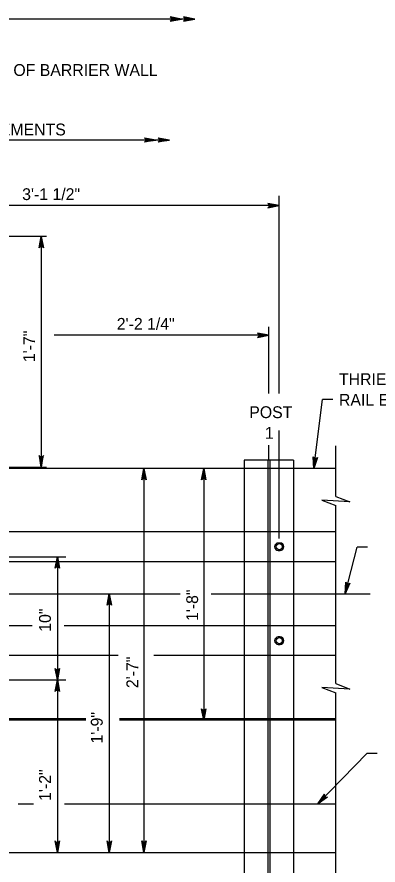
# Model space of a CAD drawing. Extents: x 632007860 to 635435983, y 295418622 to 297794622.
# Drawn here: x 634021018 to 634113990, y 295535766 to 295754298 of the extents above; entities that cross this region are included whole.
import ezdxf

# ---------------------------------------------------------------- set-up
doc = ezdxf.new("R2010")
doc.units = 0
for name, color, linetype in [('8', 7, 'Continuous'), ('S-ABUT', 7, 'Continuous'), ('S-DETL-DIMS', 7, 'Continuous'), ('S-DETL-T120', 7, 'Continuous'), ('S-STEL', 7, 'Continuous')]:
    doc.layers.add(name, color=color, linetype=linetype)

msp = doc.modelspace()

# ---------------------------------------------------------------- linework, layer by layer
at = {"layer": '8'}
for p, q in [((634085888, 295640078), (634085888, 295643944)), ((633884925, 295605683), (634063043, 295605683)), ((634070984, 295605683), (634111925, 295605683))]:
    msp.add_line(p, q, dxfattribs=at)
at = {"layer": 'S-ABUT'}
for p, q in [((634021348, 295551503), (634025281, 295551503)), ((634033228, 295551503), (634103091, 295551503)), ((634001942, 295539008), (634103091, 295539008))]:
    msp.add_line(p, q, dxfattribs=at)
at = {"layer": 'S-DETL-DIMS'}
for p, q in [((634066858, 295753743), (633896300, 295753743)), ((634060314, 295722580), (633946329, 295722580)), ((634088543, 295657244), (634088543, 295708236)), ((634088543, 295705697), (633969689, 295705697)), ((634028634, 295697741), (633925374, 295697741)), ((634027266, 295697741), (634027266, 295638295)), ((634085888, 295657266), (634085888, 295674446)), ((634085888, 295672286), (634030560, 295672286)), ((634097449, 295637961), (634099673, 295655702)), ((634102319, 295655702), (634099673, 295655702)), ((634088543, 295619944), (634088543, 295647710)), ((634103129, 295630769), (634103129, 295643821)), ((634053703, 295637960), (634053703, 295622872)), ((634069125, 295637960), (634069125, 295622872)), ((634103129, 295588901), (634103129, 295628388)), ((634053703, 295622872), (634053703, 295539008)), ((634069125, 295622872), (634069125, 295573092)), ((634105488, 295605683), (634108626, 295617710)), ((634111273, 295617710), (634108626, 295617710)), ((634002178, 295615208), (634033589, 295615208)), ((634031448, 295615208), (634031448, 295539008)), ((634040738, 295605683), (634046878, 295605683)), ((634044792, 295605683), (634044792, 295539008)), ((634103129, 295582550), (634103129, 295588901)), ((634002606, 295583470), (634033589, 295583470)), ((634103091, 295488138), (634103091, 295580169)), ((634098506, 295551530), (634111093, 295564494)), ((634113740, 295564494), (634111093, 295564494)), ((634003476, 295539008), (634043513, 295539008))]:
    msp.add_line(p, q, dxfattribs=at)
for points in [[(634063389, 295753743), (634060430, 295754298), (634060544, 295754219), (634060658, 295754140), (634060716, 295754041), (634060775, 295753942), (634060792, 295753843), (634060809, 295753743), (634060792, 295753644), (634060775, 295753545), (634060716, 295753446), (634060658, 295753346), (634060544, 295753267), (634060430, 295753188), (634063389, 295753743), (634060544, 295753267), (634060658, 295753346), (634063389, 295753743), (634060716, 295753446), (634060775, 295753545), (634063389, 295753743), (634060792, 295753644), (634060809, 295753743), (634063389, 295753743), (634060792, 295753843), (634060775, 295753942), (634063389, 295753743), (634060716, 295754041), (634060658, 295754140), (634063389, 295753743), (634060544, 295754219)], [(634066858, 295753743), (634063898, 295754298), (634064012, 295754219), (634064126, 295754140), (634064185, 295754041), (634064244, 295753942), (634064261, 295753843), (634064278, 295753743), (634064261, 295753644), (634064244, 295753545), (634064185, 295753446), (634064126, 295753346), (634064012, 295753267), (634063898, 295753188), (634066858, 295753743), (634064012, 295753267), (634064126, 295753346), (634066858, 295753743), (634064185, 295753446), (634064244, 295753545), (634066858, 295753743), (634064261, 295753644), (634064278, 295753743), (634066858, 295753743), (634064261, 295753843), (634064244, 295753942), (634066858, 295753743), (634064185, 295754041), (634064126, 295754140), (634066858, 295753743), (634064012, 295754219)], [(634056783, 295722580), (634053823, 295722025), (634053937, 295722104), (634054051, 295722183), (634054110, 295722282), (634054169, 295722382), (634054186, 295722481), (634054203, 295722580), (634054186, 295722679), (634054169, 295722779), (634054110, 295722878), (634054051, 295722977), (634053937, 295723056), (634053823, 295723135), (634056783, 295722580), (634053937, 295723056), (634054051, 295722977), (634056783, 295722580), (634054110, 295722878), (634054169, 295722779), (634056783, 295722580), (634054186, 295722679), (634054203, 295722580), (634056783, 295722580), (634054186, 295722481), (634054169, 295722382), (634056783, 295722580), (634054110, 295722282), (634054051, 295722183), (634056783, 295722580), (634053937, 295722104)], [(634060314, 295722580), (634057355, 295722025), (634057469, 295722104), (634057583, 295722183), (634057641, 295722282), (634057700, 295722382), (634057717, 295722481), (634057734, 295722580), (634057717, 295722679), (634057700, 295722779), (634057641, 295722878), (634057583, 295722977), (634057469, 295723056), (634057355, 295723135), (634060314, 295722580), (634057469, 295723056), (634057583, 295722977), (634060314, 295722580), (634057641, 295722878), (634057700, 295722779), (634060314, 295722580), (634057717, 295722679), (634057734, 295722580), (634060314, 295722580), (634057717, 295722481), (634057700, 295722382), (634060314, 295722580), (634057641, 295722282), (634057583, 295722183), (634060314, 295722580), (634057469, 295722104)], [(634088543, 295705697), (634085584, 295706252), (634085698, 295706173), (634085812, 295706094), (634085870, 295705995), (634085929, 295705896), (634085946, 295705796), (634085963, 295705697), (634085946, 295705598), (634085929, 295705499), (634085870, 295705400), (634085812, 295705300), (634085698, 295705221), (634085584, 295705142), (634088543, 295705697), (634085698, 295705221), (634085812, 295705300), (634088543, 295705697), (634085870, 295705400), (634085929, 295705499), (634088543, 295705697), (634085946, 295705598), (634085963, 295705697), (634088543, 295705697), (634085946, 295705796), (634085929, 295705896), (634088543, 295705697), (634085870, 295705995), (634085812, 295706094), (634088543, 295705697), (634085698, 295706173)], [(634027266, 295697741), (634027821, 295694781), (634027663, 295695009), (634027464, 295695127), (634027266, 295695161), (634027068, 295695127), (634026869, 295695009), (634026711, 295694781), (634027266, 295697741), (634026869, 295695009), (634027068, 295695127), (634027266, 295697741), (634027266, 295695161), (634027464, 295695127), (634027266, 295697741), (634027663, 295695009)], [(634085888, 295672286), (634082928, 295672841), (634083042, 295672762), (634083156, 295672683), (634083215, 295672584), (634083274, 295672485), (634083291, 295672386), (634083308, 295672286), (634083291, 295672187), (634083274, 295672088), (634083215, 295671989), (634083156, 295671890), (634083042, 295671811), (634082928, 295671732), (634085888, 295672286), (634083042, 295671811), (634083156, 295671890), (634085888, 295672286), (634083215, 295671989), (634083274, 295672088), (634085888, 295672286), (634083291, 295672187), (634083308, 295672286), (634085888, 295672286), (634083291, 295672386), (634083274, 295672485), (634085888, 295672286), (634083215, 295672584), (634083156, 295672683), (634085888, 295672286), (634083042, 295672762)], [(634027266, 295638295), (634027821, 295641255), (634027742, 295641141), (634027663, 295641027), (634027564, 295640968), (634027464, 295640909), (634027365, 295640892), (634027266, 295640875), (634027167, 295640892), (634027068, 295640909), (634026968, 295640968), (634026869, 295641027), (634026790, 295641141), (634026711, 295641255), (634027266, 295638295), (634026790, 295641141), (634026869, 295641027), (634027266, 295638295), (634026968, 295640968), (634027068, 295640909), (634027266, 295638295), (634027167, 295640892), (634027266, 295640875), (634027266, 295638295), (634027365, 295640892), (634027464, 295640909), (634027266, 295638295), (634027564, 295640968), (634027663, 295641027), (634027266, 295638295), (634027742, 295641141)], [(634097449, 295637961), (634097304, 295640968), (634097366, 295640845), (634097429, 295640721), (634097519, 295640649), (634097610, 295640577), (634097706, 295640547), (634097801, 295640516), (634097902, 295640520), (634098003, 295640523), (634098109, 295640568), (634098215, 295640612), (634098309, 295640715), (634098403, 295640817), (634097449, 295637961), (634098309, 295640715), (634098215, 295640612), (634097449, 295637961), (634098109, 295640568), (634098003, 295640523), (634097449, 295637961), (634097902, 295640520), (634097801, 295640516), (634097449, 295637961), (634097706, 295640547), (634097610, 295640577), (634097449, 295637961), (634097519, 295640649), (634097429, 295640721), (634097449, 295637961), (634097366, 295640845)], [(634053703, 295637960), (634054258, 295635001), (634054100, 295635229), (634053902, 295635346), (634053703, 295635380), (634053505, 295635346), (634053307, 295635229), (634053149, 295635001), (634053703, 295637960), (634053307, 295635229), (634053505, 295635346), (634053703, 295637960), (634053703, 295635380), (634053902, 295635346), (634053703, 295637960), (634054100, 295635229)], [(634069125, 295637960), (634069680, 295635001), (634069522, 295635229), (634069324, 295635346), (634069125, 295635380), (634068927, 295635346), (634068729, 295635229), (634068571, 295635001), (634069125, 295637960), (634068729, 295635229), (634068927, 295635346), (634069125, 295637960), (634069125, 295635380), (634069324, 295635346), (634069125, 295637960), (634069522, 295635229)], [(634103129, 295630769), (634106700, 295629319), (634099557, 295629751), (634103129, 295628388)], [(634031448, 295615208), (634032002, 295612248), (634031923, 295612362), (634031844, 295612476), (634031745, 295612535), (634031646, 295612594), (634031547, 295612611), (634031448, 295612628), (634031348, 295612611), (634031249, 295612594), (634031150, 295612535), (634031051, 295612476), (634030972, 295612362), (634030893, 295612248), (634031448, 295615208), (634030972, 295612362), (634031051, 295612476), (634031448, 295615208), (634031150, 295612535), (634031249, 295612594), (634031448, 295615208), (634031348, 295612611), (634031448, 295612628), (634031448, 295615208), (634031547, 295612611), (634031646, 295612594), (634031448, 295615208), (634031745, 295612535), (634031844, 295612476), (634031448, 295615208), (634031923, 295612362)], [(634105488, 295605683), (634105698, 295608686), (634105746, 295608556), (634105794, 295608426), (634105875, 295608344), (634105956, 295608262), (634106048, 295608220), (634106139, 295608179), (634106240, 295608170), (634106340, 295608162), (634106451, 295608193), (634106562, 295608225), (634106667, 295608316), (634106772, 295608406), (634105488, 295605683), (634106667, 295608316), (634106562, 295608225), (634105488, 295605683), (634106451, 295608193), (634106340, 295608162), (634105488, 295605683), (634106240, 295608170), (634106139, 295608179), (634105488, 295605683), (634106048, 295608220), (634105956, 295608262), (634105488, 295605683), (634105875, 295608344), (634105794, 295608426), (634105488, 295605683), (634105746, 295608556)], [(634044792, 295605683), (634045347, 295602723), (634045268, 295602837), (634045189, 295602951), (634045090, 295603010), (634044990, 295603069), (634044891, 295603086), (634044792, 295603103), (634044693, 295603086), (634044593, 295603069), (634044494, 295603010), (634044395, 295602951), (634044316, 295602837), (634044237, 295602723), (634044792, 295605683), (634044316, 295602837), (634044395, 295602951), (634044792, 295605683), (634044494, 295603010), (634044593, 295603069), (634044792, 295605683), (634044693, 295603086), (634044792, 295603103), (634044792, 295605683), (634044891, 295603086), (634044990, 295603069), (634044792, 295605683), (634045090, 295603010), (634045189, 295602951), (634044792, 295605683), (634045268, 295602837)], [(634031448, 295583470), (634030893, 295586430), (634030972, 295586316), (634031051, 295586202), (634031150, 295586143), (634031249, 295586084), (634031348, 295586067), (634031448, 295586050), (634031547, 295586067), (634031646, 295586084), (634031745, 295586143), (634031844, 295586202), (634031923, 295586316), (634032002, 295586430), (634031448, 295583470), (634031923, 295586316), (634031844, 295586202), (634031448, 295583470), (634031745, 295586143), (634031646, 295586084), (634031448, 295583470), (634031547, 295586067), (634031448, 295586050), (634031448, 295583470), (634031348, 295586067), (634031249, 295586084), (634031448, 295583470), (634031150, 295586143), (634031051, 295586202), (634031448, 295583470), (634030972, 295586316)], [(634031448, 295583470), (634032002, 295580511), (634031923, 295580625), (634031844, 295580739), (634031745, 295580798), (634031646, 295580857), (634031547, 295580874), (634031448, 295580891), (634031348, 295580874), (634031249, 295580857), (634031150, 295580798), (634031051, 295580739), (634030972, 295580625), (634030893, 295580511), (634031448, 295583470), (634030972, 295580625), (634031051, 295580739), (634031448, 295583470), (634031150, 295580798), (634031249, 295580857), (634031448, 295583470), (634031348, 295580874), (634031448, 295580891), (634031448, 295583470), (634031547, 295580874), (634031646, 295580857), (634031448, 295583470), (634031745, 295580798), (634031844, 295580739), (634031448, 295583470), (634031923, 295580625)], [(634103129, 295582550), (634106700, 295581100), (634099557, 295581532), (634103129, 295580169)], [(634069125, 295573092), (634068571, 295576051), (634068729, 295575823), (634068927, 295575706), (634069125, 295575672), (634069324, 295575706), (634069522, 295575823), (634069680, 295576051), (634069125, 295573092), (634069522, 295575823), (634069324, 295575706), (634069125, 295573092), (634069125, 295575672), (634068927, 295575706), (634069125, 295573092), (634068729, 295575823)], [(634098506, 295551530), (634100179, 295554034), (634100155, 295553897), (634100132, 295553760), (634100162, 295553649), (634100192, 295553538), (634100251, 295553456), (634100310, 295553374), (634100393, 295553317), (634100476, 295553260), (634100588, 295553233), (634100700, 295553205), (634100836, 295553232), (634100972, 295553258), (634098506, 295551530), (634100836, 295553232), (634100700, 295553205), (634098506, 295551530), (634100588, 295553233), (634100476, 295553260), (634098506, 295551530), (634100393, 295553317), (634100310, 295553374), (634098506, 295551530), (634100251, 295553456), (634100192, 295553538), (634098506, 295551530), (634100162, 295553649), (634100132, 295553760), (634098506, 295551530), (634100155, 295553897)], [(634031448, 295539008), (634030893, 295541967), (634030972, 295541853), (634031051, 295541739), (634031150, 295541680), (634031249, 295541621), (634031348, 295541604), (634031448, 295541587), (634031547, 295541604), (634031646, 295541621), (634031745, 295541680), (634031844, 295541739), (634031923, 295541853), (634032002, 295541967), (634031448, 295539008), (634031923, 295541853), (634031844, 295541739), (634031448, 295539008), (634031745, 295541680), (634031646, 295541621), (634031448, 295539008), (634031547, 295541604), (634031448, 295541587), (634031448, 295539008), (634031348, 295541604), (634031249, 295541621), (634031448, 295539008), (634031150, 295541680), (634031051, 295541739), (634031448, 295539008), (634030972, 295541853)], [(634031448, 295539008), (634030893, 295541967), (634030972, 295541853), (634031051, 295541739), (634031150, 295541680), (634031249, 295541621), (634031348, 295541604), (634031448, 295541587), (634031547, 295541604), (634031646, 295541621), (634031745, 295541680), (634031844, 295541739), (634031923, 295541853), (634032002, 295541967), (634031448, 295539008), (634031923, 295541853), (634031844, 295541739), (634031448, 295539008), (634031745, 295541680), (634031646, 295541621), (634031448, 295539008), (634031547, 295541604), (634031448, 295541587), (634031448, 295539008), (634031348, 295541604), (634031249, 295541621), (634031448, 295539008), (634031150, 295541680), (634031051, 295541739), (634031448, 295539008), (634030972, 295541853)], [(634044792, 295539008), (634044237, 295541967), (634044316, 295541853), (634044395, 295541739), (634044494, 295541680), (634044593, 295541621), (634044693, 295541604), (634044792, 295541587), (634044891, 295541604), (634044990, 295541621), (634045090, 295541680), (634045189, 295541739), (634045268, 295541853), (634045347, 295541967), (634044792, 295539008), (634045268, 295541853), (634045189, 295541739), (634044792, 295539008), (634045090, 295541680), (634044990, 295541621), (634044792, 295539008), (634044891, 295541604), (634044792, 295541587), (634044792, 295539008), (634044693, 295541604), (634044593, 295541621), (634044792, 295539008), (634044494, 295541680), (634044395, 295541739), (634044792, 295539008), (634044316, 295541853)], [(634044792, 295539008), (634044237, 295541967), (634044316, 295541853), (634044395, 295541739), (634044494, 295541680), (634044593, 295541621), (634044693, 295541604), (634044792, 295541587), (634044891, 295541604), (634044990, 295541621), (634045090, 295541680), (634045189, 295541739), (634045268, 295541853), (634045347, 295541967), (634044792, 295539008), (634045268, 295541853), (634045189, 295541739), (634044792, 295539008), (634045090, 295541680), (634044990, 295541621), (634044792, 295539008), (634044891, 295541604), (634044792, 295541587), (634044792, 295539008), (634044693, 295541604), (634044593, 295541621), (634044792, 295539008), (634044494, 295541680), (634044395, 295541739), (634044792, 295539008), (634044316, 295541853)], [(634053703, 295539008), (634053149, 295541967), (634053307, 295541739), (634053505, 295541621), (634053703, 295541587), (634053902, 295541621), (634054100, 295541739), (634054258, 295541967), (634053703, 295539008), (634054100, 295541739), (634053902, 295541621), (634053703, 295539008), (634053703, 295541587), (634053505, 295541621), (634053703, 295539008), (634053307, 295541739)]]:
    msp.add_lwpolyline(points, dxfattribs=at)
at = {"layer": 'S-STEL'}
for p, q in [((634092245, 295640078), (634079530, 295640078)), ((634079530, 295640078), (634079530, 295637960)), ((634085623, 295640078), (634085623, 295531427)), ((634086152, 295640078), (634086152, 295532811)), ((634092245, 295640078), (634092245, 295637960)), ((634103129, 295637960), (633898237, 295637960)), ((633999549, 295638295), (634028634, 295638295)), ((634079530, 295637960), (634079530, 295573405)), ((634092245, 295637960), (634092245, 295573405)), ((634103129, 295621623), (633925601, 295621623)), ((634087360, 295617796), (634087360, 295617779)), ((634087360, 295617796), (634087360, 295617779)), ((634088780, 295618742), (634088306, 295618742)), ((634088780, 295618742), (634088306, 295618742)), ((634089726, 295617779), (634089726, 295617796)), ((634089726, 295617779), (634089726, 295617796)), ((634088306, 295616833), (634088780, 295616833)), ((634088306, 295616833), (634088780, 295616833)), ((634103129, 295613928), (633970096, 295613928)), ((634024942, 295597436), (633926872, 295597436)), ((634103091, 295597436), (634033159, 295597436)), ((634088780, 295594533), (634088306, 295594533)), ((634087360, 295593587), (634087360, 295593571)), ((634088306, 295592624), (634088780, 295592624)), ((634089726, 295593571), (634089726, 295593587)), ((634047084, 295589741), (633970563, 295589741)), ((634103091, 295589741), (634056234, 295589741)), ((634038766, 295573092), (633893231, 295573092)), ((634038766, 295573404), (633898237, 295573404)), ((634103091, 295573404), (634047435, 295573404)), ((634103091, 295573092), (634047435, 295573092)), ((634079530, 295573405), (634079530, 295551503)), ((634092245, 295573405), (634092245, 295551503)), ((634079530, 295551503), (634079530, 295529478)), ((634092245, 295551503), (634092245, 295529478))]:
    msp.add_line(p, q, dxfattribs=at)
for centre in [(634088543, 295617787), (634088543, 295593579)]:
    msp.add_circle(centre, 794, dxfattribs=at)
for centre, start, end in [((634088306, 295617796), 90, 180), ((634088306, 295617796), 90, 180), ((634088306, 295617779), 180, 270), ((634088306, 295617779), 180, 270), ((634088780, 295617796), 0, 90), ((634088780, 295617796), 0, 90), ((634088780, 295617779), 270, 360), ((634088780, 295617779), 270, 360), ((634088306, 295593587), 90, 180), ((634088780, 295593587), 0, 90), ((634088306, 295593571), 180, 270), ((634088780, 295593571), 270, 360)]:
    msp.add_arc(centre, 946, start, end, dxfattribs=at)

# ---------------------------------------------------------------- texts
at = {"layer": 'S-DETL-T120'}
for s, height, p in [('END OF BARRIER WALL', 3048.01, (634010352, 295739103)), ('NESTED THRIE-BEAM RAIL ELEMENTS', 3048.07, (633957497, 295723780)), ('3\'-1 1/2"', 3048, (634022357, 295707111)), ('2\'-2 1/4"', 3048, (634046717, 295673690)), ('THRIE-BEAM ', 3048.01, (634103931, 295659447)), ('RAIL ELEMENT', 3048.01, (634103931, 295654113)), ('POST', 3048, (634080834, 295650930)), ('1', 3048, (634084854, 295645596))]:
    msp.add_text(s, height=height, dxfattribs=at).set_placement(p)
for s, p in [('1\'-7"', (634025680, 295665354)), ('1\'-8"', (634067667, 295598651)), ('10"', (634029747, 295595880)), ('2\'-7"', (634052245, 295581352)), ('1\'-9"', (634043092, 295567079)), ('1\'-2"', (634029747, 295552298))]:
    msp.add_text(s, height=3048, rotation=90, dxfattribs=at).set_placement(p)

doc.saveas('drawing.dxf')
